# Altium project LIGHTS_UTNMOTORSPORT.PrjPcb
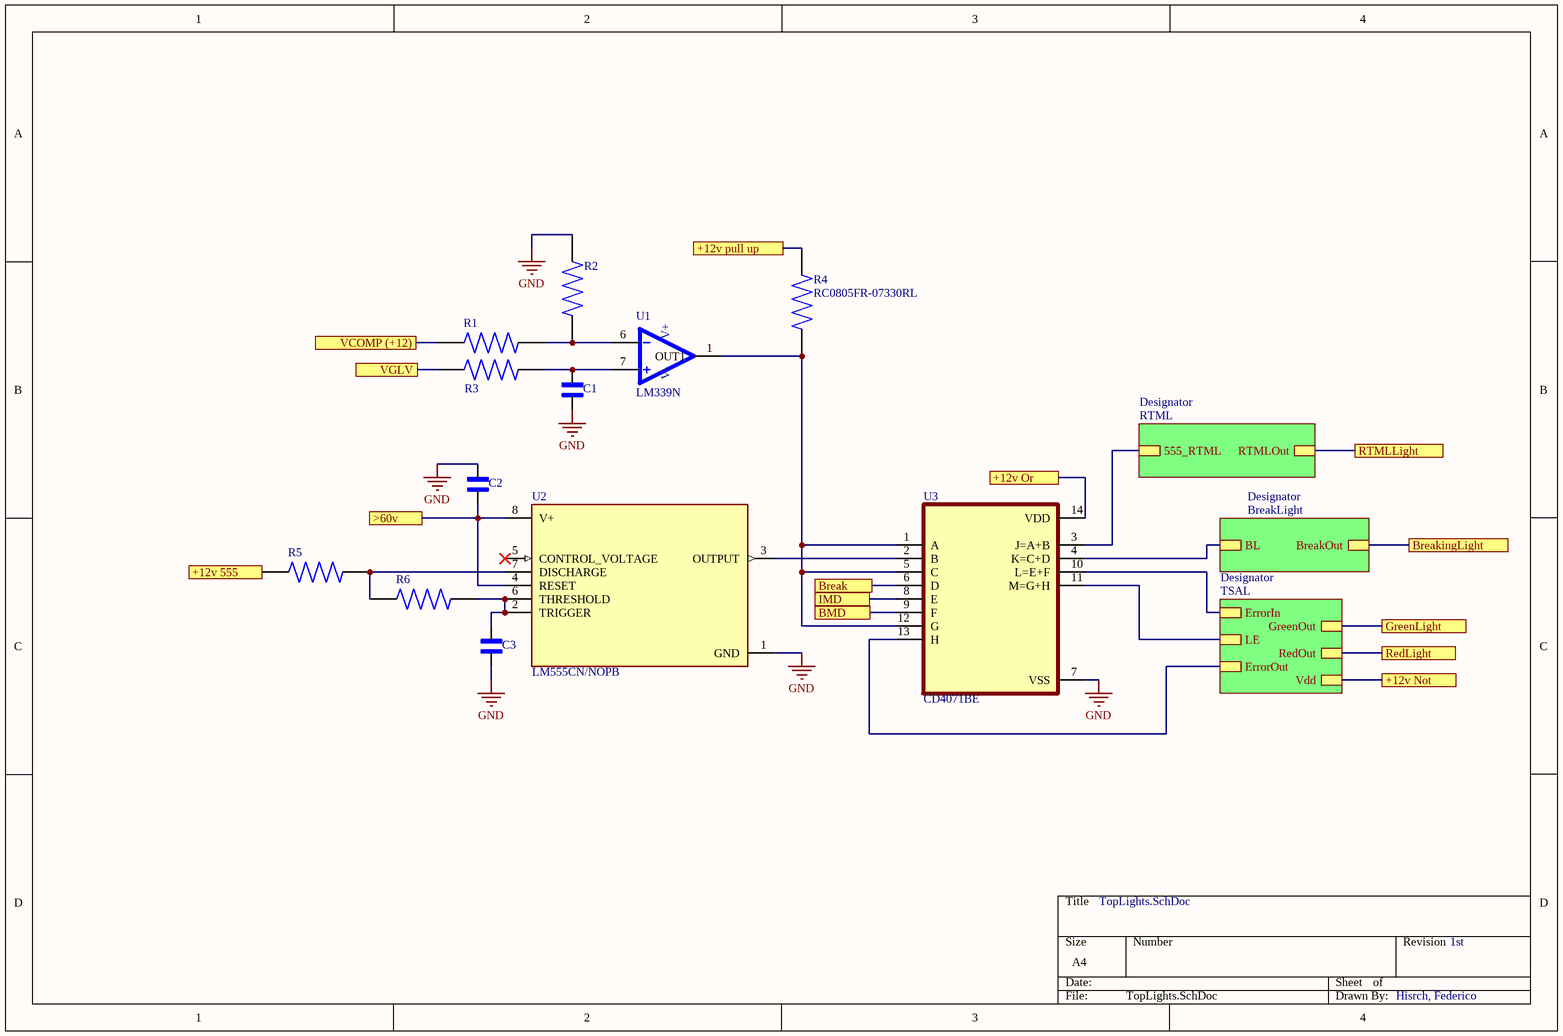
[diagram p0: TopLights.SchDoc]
4 sheets, 26 parts. Net scope: hierarchical (ports join the sheet entries above them; power ports are global).
Sheets:
  TopLights.SchDoc
    Designator = BreakLight.SchDoc
    Designator = RTML.SchDoc
    Designator = TSAL.SchDoc

## Sheet TopLights.SchDoc
size A4; SheetNumber: 1; SheetTotal: 4

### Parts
C1  08055C104M4T2A  [CAPC2012X140N]  (value not drawn)
C2  08055C104M4T2A  [CAPC2012X140N]  (value not drawn)
C3  08055C104M4T2A  [CAPC2012X140N]  (value not drawn)
R1  RC0805FR-07330RL  [RESC2012X60N]  (value not drawn)
R2  RC0805FR-07330RL  [RESC2012X60N]  (value not drawn)
R3  RC0805FR-07330RL  [RESC2012X60N]  (value not drawn)
R4  RC0805FR-07330RL  [RESC2012X60N]
R5  RC0805FR-07330RL  [RESC2012X60N]  (value not drawn)
R6  RC0805FR-07330RL  [RESC2012X60N]  (value not drawn)
U1  LM339N  [DIP764W47P254L1920H431Q14]
U2  LM555CN/NOPB  [DIP794W45P254L959H508Q8]
U3  CD4071BE  [DIP794W45P254L1969H508Q14]

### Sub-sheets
Designator = BreakLight: BL, BreakOut
Designator = RTML: 555_RTML, RTMLOut
Designator = TSAL: ErrorIn, ErrorOut, GreenOut, RedOut, LE, Vdd

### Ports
+12v 555, +12v Not, +12v Or, +12v pull up, >60v, BMD, Break, BreakingLight, GreenLight, IMD, RedLight, RTMLLight, VCOMP (+12), VGLV

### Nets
GND: C1.2 C2.1 C3.2 R2.2 U2.1(GND) U3.7(VSS)
NetC1_1: C1.1 R3.2 U1.7(IN1+)
NetC2_2: C2.2 U2.4(RESET) U2.8(V+) ; port >60v
NetC3_1: C3.1 R6.2 U2.2(TRIGGER) U2.6(THRESHOLD)
NetC4_2: U3.10(L=E+F) ; sheet Designator/ErrorIn
NetQ1_1: U3.4(K=C+D) ; sheet Designator/BL
NetQ1_2: port BreakingLight, sheet Designator/BreakOut
NetQ2_1: U3.3(J=A+B) ; sheet Designator/555_RTML
NetQ2_2: port RTMLLight, sheet Designator/RTMLOut
NetQ3_2: port GreenLight, sheet Designator/GreenOut
NetQ4_1: U3.11(M=G+H) ; sheet Designator/LE
NetQ4_2: port RedLight, sheet Designator/RedOut
NetR1_1: R1.1 ; port VCOMP (+12)
NetR1_2: R1.2 R2.1 U1.6(IN1-)
NetR3_1: R3.1 ; port VGLV
NetR4_1: R4.1 U1.1(OUT1) U3.1(A) U3.5(C) U3.12(G)
NetR4_2: R4.2 ; port +12v pull up
NetR5_1: R5.1 ; port +12v 555
NetR5_2: R5.2 R6.1 U2.7(DISCHARGE)
NetU2_3: U2.3(OUTPUT) U3.2(B)
NetU3_6: U3.6(D) ; port Break
NetU3_8: U3.8(E) ; port IMD
NetU3_9: U3.9(F) ; port BMD
NetU3_13: U3.13(H) ; sheet Designator/ErrorOut
NetU3_14: U3.14(VDD) ; port +12v Or
NetU4_14: port +12v Not, sheet Designator/Vdd

Not connected (* = marked no-connect by the designer): U2 5(CONTROL_VOLTAGE)*

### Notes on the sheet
- TopLights.SchDoc
- 1st
- Hisrch, Federico

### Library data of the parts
C1-C3 = 08055C104M4T2A: 0.1 ÂµF Â±20% 50V Ceramic Capacitor X7R 0805 (2012 Metric); MF: AVX
R1-R6 = RC0805FR-07330RL: 330 Ohms Â±1% 0.125W, 1/8W Chip Resistor 0805 (2012 Metric) Moisture Resistant Thick Film; MF: Yageo
U1 = LM339N: Quad Voltage Comparators; MF: TAEJIN
U2 = LM555CN/NOPB: Highly Stable 555 Timer; MF: Texas Instruments
U3 = CD4071BE: 4-ch 2-input 3-V to 18-V OR gate; MF: Texas Instruments

## Sheet BreakLight.SchDoc
size A4; SheetNumber: 2; SheetTotal: 4
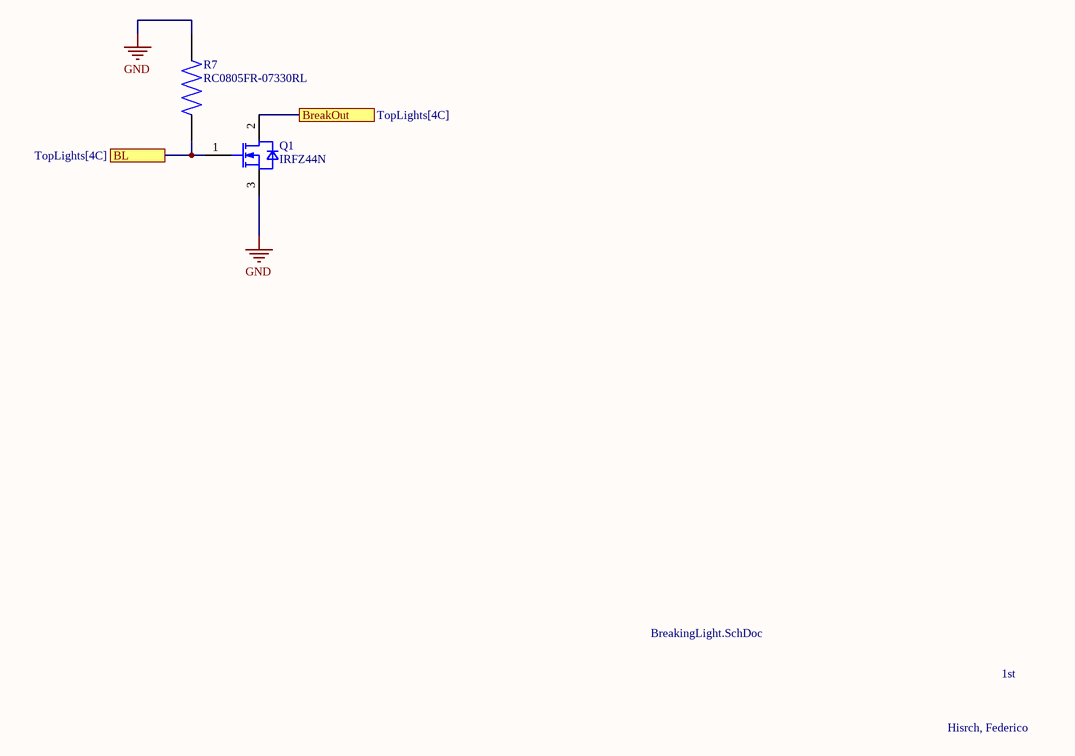
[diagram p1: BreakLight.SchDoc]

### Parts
Q1  IRFZ44N  [IFX-PG-TO220-3-904-1]
R7  RC0805FR-07330RL  [RESC2012X60N]

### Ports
BL (see TopLights[4C]), BreakOut (see TopLights[4C])

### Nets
GND: Q1.3(SOURCE) R7.2
NetQ1_1: Q1.1(GATE) R7.1 ; port BL
NetQ1_2: Q1.2(DRAIN) ; port BreakOut

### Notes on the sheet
- BreakingLight.SchDoc
- 1st
- Hisrch, Federico

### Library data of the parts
Q1 = IRFZ44N: OptiMOS 3 Power-Transistor, VDS 100V; Manufacturer: Infineon Technologies
R7 = RC0805FR-07330RL: as R1 on sheet TopLights

## Sheet RTML.SchDoc
size A4; SheetNumber: 3; SheetTotal: 4
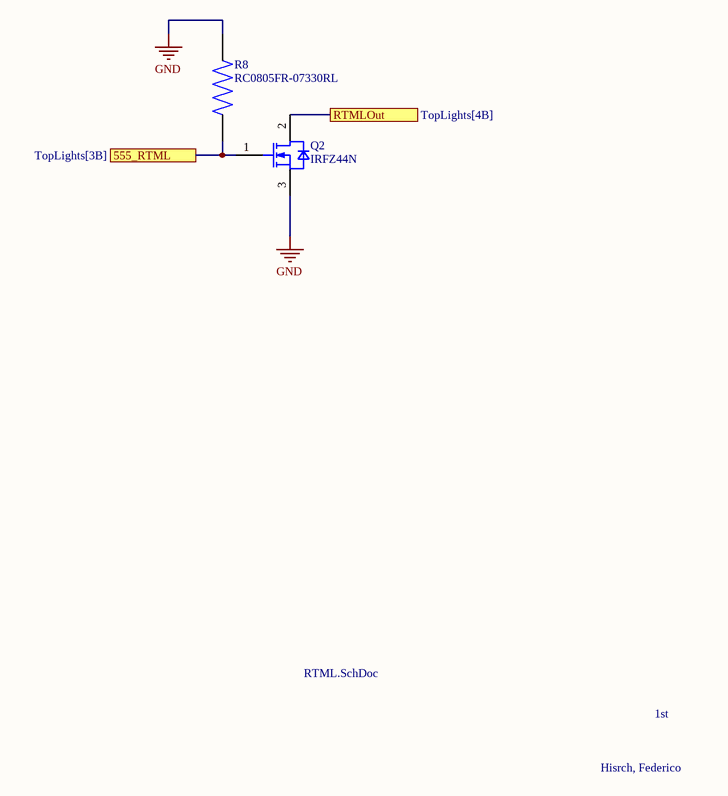
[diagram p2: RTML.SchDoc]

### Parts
Q2  IRFZ44N  [IFX-PG-TO220-3-904-1]
R8  RC0805FR-07330RL  [RESC2012X60N]

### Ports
555_RTML (see TopLights[3B]), RTMLOut (see TopLights[4B])

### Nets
GND: Q2.3(SOURCE) R8.2
NetQ2_1: Q2.1(GATE) R8.1 ; port 555_RTML
NetQ2_2: Q2.2(DRAIN) ; port RTMLOut

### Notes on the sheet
- RTML.SchDoc
- 1st
- Hisrch, Federico

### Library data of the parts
Q2 = IRFZ44N: as Q1 on sheet BreakLight
R8 = RC0805FR-07330RL: as R1 on sheet TopLights

## Sheet TSAL.SchDoc
size A4; SheetNumber: 4; SheetTotal: 4
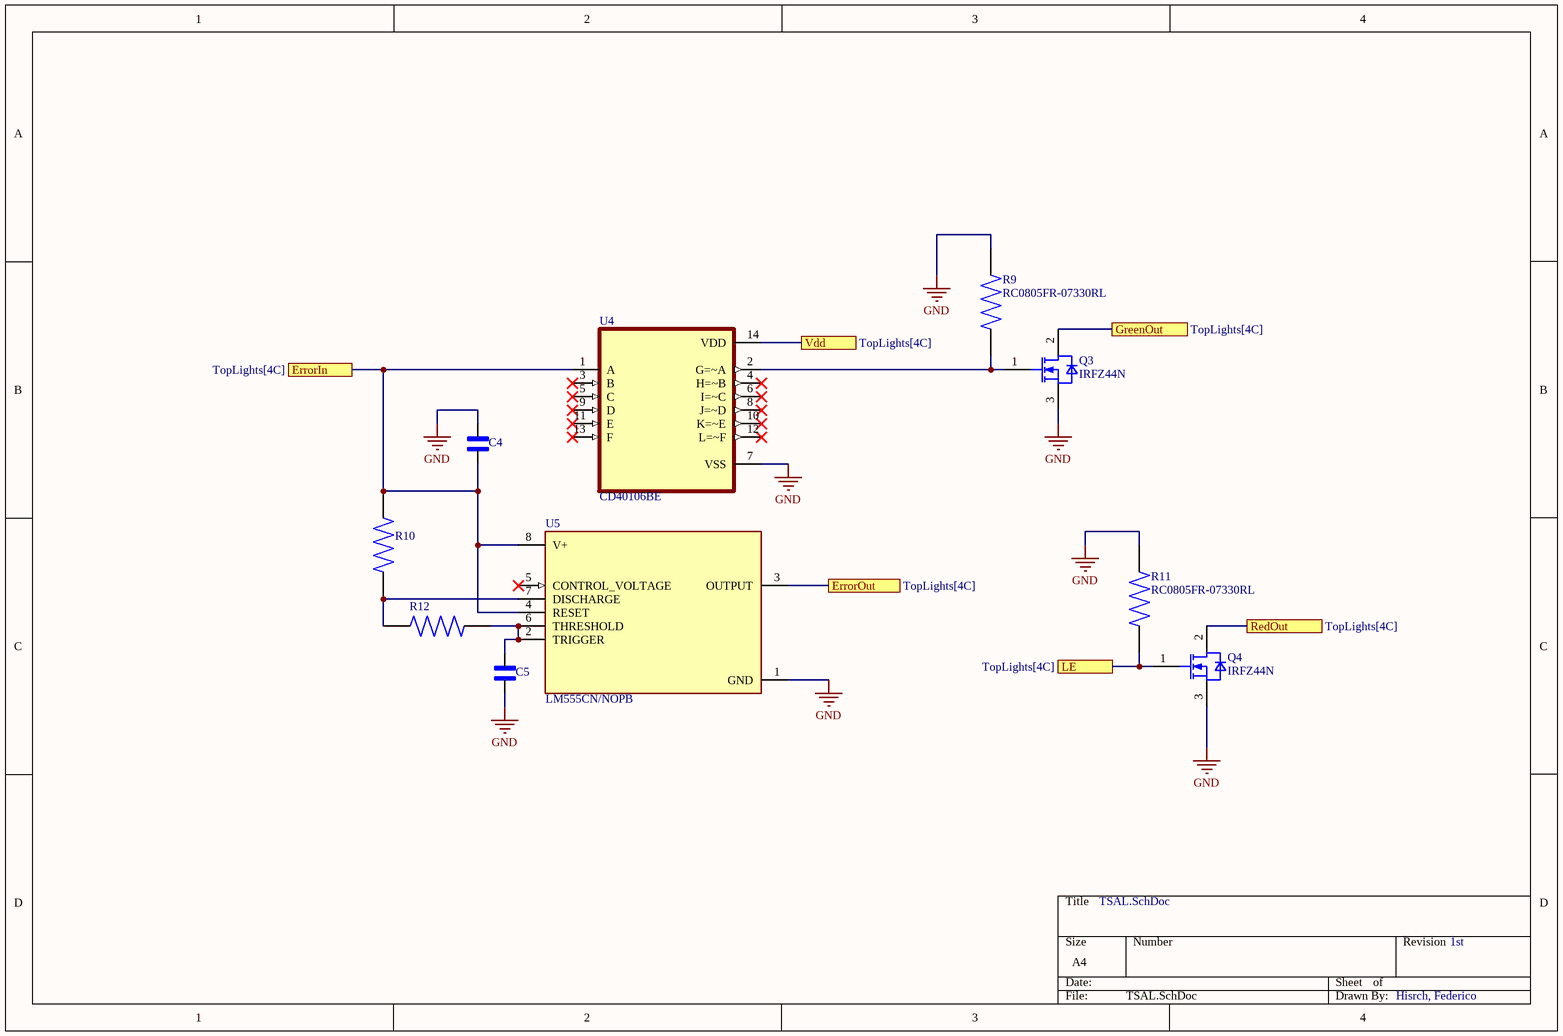
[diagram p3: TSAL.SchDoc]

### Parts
C4  08055C104M4T2A  [CAPC2012X140N]  (value not drawn)
C5  08055C104M4T2A  [CAPC2012X140N]  (value not drawn)
Q3  IRFZ44N  [IFX-PG-TO220-3-904-1]
Q4  IRFZ44N  [IFX-PG-TO220-3-904-1]
R9  RC0805FR-07330RL  [RESC2012X60N]
R10  RC0805FR-07330RL  [RESC2012X60N]  (value not drawn)
R11  RC0805FR-07330RL  [RESC2012X60N]
R12  RC0805FR-07330RL  [RESC2012X60N]  (value not drawn)
U4  CD40106BE  [DIP794W45P254L1969H508Q14]
U5  LM555CN/NOPB  [DIP794W45P254L959H508Q8]

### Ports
ErrorIn (see TopLights[4C]), ErrorOut (see TopLights[4C]), GreenOut (see TopLights[4C]), LE (see TopLights[4C]), RedOut (see TopLights[4C]), Vdd (see TopLights[4C])

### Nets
GND: C4.1 C5.2 Q3.3(SOURCE) Q4.3(SOURCE) R9.2 R11.2 U4.7(VSS) U5.1(GND)
NetC4_2: C4.2 R10.1 U4.1(A) U5.4(RESET) U5.8(V+) ; port ErrorIn
NetC5_1: C5.1 R12.2 U5.2(TRIGGER) U5.6(THRESHOLD)
NetQ3_1: Q3.1(GATE) R9.1 U4.2(G=~A)
NetQ3_2: Q3.2(DRAIN) ; port GreenOut
NetQ4_1: Q4.1(GATE) R11.1 ; port LE
NetQ4_2: Q4.2(DRAIN) ; port RedOut
NetR10_2: R10.2 R12.1 U5.7(DISCHARGE)
NetU3_13: U5.3(OUTPUT) ; port ErrorOut
NetU4_14: U4.14(VDD) ; port Vdd

Not connected (* = marked no-connect by the designer): U4 3(B)* 4(H=~B)* 5(C)* 6(I=~C)* 8(J=~D)* 9(D)* 10(K=~E)* 11(E)* 12(L=~F)* 13(F)*; U5 5(CONTROL_VOLTAGE)*

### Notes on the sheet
- TSAL.SchDoc
- 1st
- Hisrch, Federico

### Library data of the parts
C4 C5 = 08055C104M4T2A: as C1 on sheet TopLights
Q3 Q4 = IRFZ44N: as Q1 on sheet BreakLight
R9-R12 = RC0805FR-07330RL: as R1 on sheet TopLights
U4 = CD40106BE: 6-ch, 3-V to 18-V inverters with Schmitt-Trigger inputs; MF: Texas Instruments
U5 = LM555CN/NOPB: as U2 on sheet TopLights

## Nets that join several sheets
GND: TopLights (6 pins), BreakLight (Q1.3 R7.2), RTML (Q2.3 R8.2), TSAL (8 pins)
NetC4_2: TopLights (U3.10), TSAL (5 pins)
NetQ1_1: TopLights (U3.4), BreakLight (Q1.1 R7.1)
NetQ2_1: TopLights (U3.3), RTML (Q2.1 R8.1)
NetQ4_1: TopLights (U3.11), TSAL (Q4.1 R11.1)
NetU3_13: TopLights (U3.13), TSAL (U5.3)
